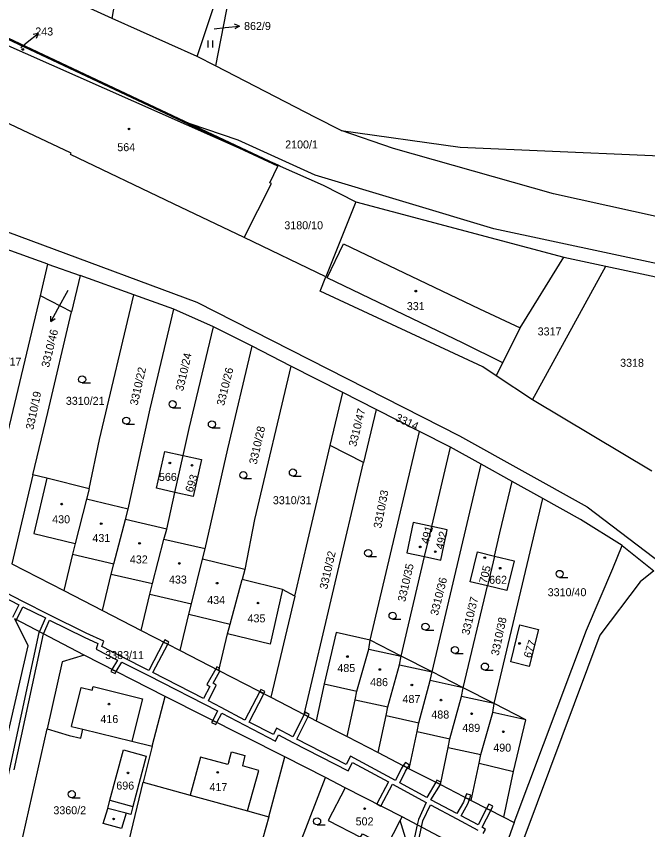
# Model space of a CAD drawing. Extents: x -776734 to -748832, y -1118122 to -976986.
# Drawn here: x -752629.9 to -752495.8, y -1114435.8 to -1114263.1 of the extents above; entities that cross this region are included whole.
import ezdxf

# ---------------------------------------------------------------- set-up
doc = ezdxf.new("R2010")
doc.units = 0
for name, color, linetype in [('KM_Hranice obce', 7, 'Continuous'), ('KM_Hranice parcel', 7, 'Continuous'), ('KM_Parcelní čísla', 7, 'Continuous'), ('KM_Pop  PČ popisy', 7, 'Continuous'), ('KM_Vnitřní kresba', 7, 'Continuous'), ('KM_Věcná břemena k části', 7, 'Continuous'), ('KM_Značky budov', 7, 'Continuous'), ('KM_Značky kultur', 7, 'Continuous')]:
    doc.layers.add(name, color=color, linetype=linetype)

msp = doc.modelspace()

# ---------------------------------------------------------------- linework, layer by layer
at = {"layer": 'KM_Hranice obce'}
for p, q in [((-752573.84, -1114294.91), (-752574.27, -1114294.72)), ((-752573.84, -1114294.91), (-752574.27, -1114294.72)), ((-752557.76, -1114302.48), (-752513.59, -1114314.26)), ((-752557.76, -1114302.48), (-752513.59, -1114314.26)), ((-752513.59, -1114314.26), (-752504.69, -1114316.16)), ((-752513.59, -1114314.26), (-752504.69, -1114316.16)), ((-752504.69, -1114316.16), (-752479.17, -1114321.6)), ((-752504.69, -1114316.16), (-752479.17, -1114321.6))]:
    msp.add_line(p, q, dxfattribs=at)
for points in [[(-752574.27, -1114294.72), (-752582.54, -1114291.06), (-752633.55, -1114268.51)], [(-752574.27, -1114294.72), (-752582.54, -1114291.06), (-752633.55, -1114268.51)], [(-752573.84, -1114294.91), (-752564.71, -1114298.94), (-752557.76, -1114302.48)], [(-752573.84, -1114294.91), (-752564.71, -1114298.94), (-752557.76, -1114302.48)]]:
    msp.add_lwpolyline(points, dxfattribs=at)
at = {"layer": 'KM_Hranice parcel'}
for p, q in [((-752609.53, -1114263.52), (-752605.61, -1114240.78)), ((-752591.45, -1114271.64), (-752581.12, -1114240.48)), ((-752581.12, -1114240.48), (-752587.58, -1114273.63)), ((-752609.53, -1114263.52), (-752614.99, -1114261.06)), ((-752591.45, -1114271.64), (-752609.53, -1114263.52)), ((-752587.58, -1114273.63), (-752591.45, -1114271.64)), ((-752557.76, -1114302.48), (-752564.12, -1114318.38)), ((-752564.12, -1114318.38), (-752581.45, -1114310.09)), ((-752623.16, -1114315.69), (-752632.76, -1114312.25)), ((-752624.76, -1114322.41), (-752623.16, -1114315.69)), ((-752623.16, -1114315.69), (-752616.33, -1114318.14)), ((-752520.23, -1114344.55), (-752504.69, -1114316.16)), ((-752616.33, -1114318.14), (-752618.14, -1114325.82)), ((-752604.94, -1114322.22), (-752616.33, -1114318.14)), ((-752565.36, -1114321.48), (-752564.12, -1114318.38)), ((-752632.38, -1114354.51), (-752624.76, -1114322.41)), ((-752618.14, -1114325.82), (-752624.76, -1114322.41)), ((-752596.44, -1114325.26), (-752604.94, -1114322.22)), ((-752587.97, -1114329), (-752596.44, -1114325.26)), ((-752579.81, -1114333.15), (-752587.97, -1114329)), ((-752571.56, -1114337.35), (-752579.81, -1114333.15)), ((-752560.54, -1114342.95), (-752571.56, -1114337.35)), ((-752520.23, -1114344.55), (-752527.93, -1114339.43)), ((-752563.2, -1114354.2), (-752560.54, -1114342.95)), ((-752553.44, -1114346.57), (-752560.54, -1114342.95)), ((-752494.88, -1114359.71), (-752520.23, -1114344.55)), ((-752553.44, -1114346.57), (-752556.11, -1114357.85)), ((-752544.26, -1114351.24), (-752553.44, -1114346.57)), ((-752554.74, -1114395.57), (-752544.26, -1114351.24)), ((-752537.67, -1114354.58), (-752544.26, -1114351.24)), ((-752556.11, -1114357.85), (-752563.2, -1114354.2)), ((-752541.65, -1114371.44), (-752537.67, -1114354.58)), ((-752531.12, -1114358.22), (-752537.67, -1114354.58)), ((-752596.18, -1114364.2), (-752594.42, -1114356.36)), ((-752568.76, -1114411.33), (-752556.11, -1114357.85)), ((-752541.56, -1114402.3), (-752531.12, -1114358.22)), ((-752524.6, -1114361.84), (-752531.12, -1114358.22)), ((-752626.32, -1114360.46), (-752630.78, -1114379.36)), ((-752518.06, -1114365.48), (-752524.6, -1114361.84)), ((-752614.36, -1114363.4), (-752614.94, -1114365.65)), ((-752606.12, -1114367.71), (-752614.94, -1114365.65)), ((-752597.93, -1114371.96), (-752596.18, -1114364.2)), ((-752528.37, -1114409.03), (-752518.06, -1114365.48)), ((-752606.7, -1114369.93), (-752606.12, -1114367.71)), ((-752597.93, -1114371.96), (-752606.7, -1114369.93)), ((-752598.5, -1114374.19), (-752597.93, -1114371.96)), ((-752543.16, -1114377.83), (-752541.65, -1114371.44)), ((-752589.73, -1114376.15), (-752598.5, -1114374.19)), ((-752590.29, -1114378.38), (-752589.73, -1114376.15)), ((-752501.24, -1114375.49), (-752494.46, -1114380.82)), ((-752548.15, -1114398.93), (-752543.16, -1114377.83)), ((-752533.49, -1114383.17), (-752531.93, -1114376.8)), ((-752531.93, -1114376.8), (-752528.34, -1114377.69)), ((-752528.34, -1114377.69), (-752529.84, -1114384.01)), ((-752528.34, -1114377.69), (-752524.11, -1114378.74)), ((-752630.78, -1114379.36), (-752619.77, -1114385.04)), ((-752581.34, -1114380.54), (-752590.29, -1114378.38)), ((-752524.11, -1114378.74), (-752525.69, -1114385.04)), ((-752581.34, -1114380.54), (-752581.91, -1114382.66)), ((-752534.96, -1114405.67), (-752529.84, -1114384.01)), ((-752529.84, -1114384.01), (-752533.49, -1114383.17)), ((-752525.69, -1114385.04), (-752529.84, -1114384.01)), ((-752619.77, -1114385.04), (-752611.55, -1114389.28)), ((-752570.75, -1114386.2), (-752575.83, -1114407.69)), ((-752611.55, -1114389.28), (-752603.32, -1114393.52)), ((-752615.48, -1114398.75), (-752630.14, -1114391.02)), ((-752603.32, -1114393.52), (-752595.07, -1114397.77)), ((-752548.15, -1114398.93), (-752554.74, -1114395.57)), ((-752595.07, -1114397.77), (-752586.84, -1114402.01)), ((-752598.27, -1114407.53), (-752615.48, -1114398.75)), ((-752541.56, -1114402.3), (-752548.15, -1114398.93)), ((-752586.84, -1114402.01), (-752575.83, -1114407.69)), ((-752534.96, -1114405.67), (-752541.56, -1114402.3)), ((-752528.37, -1114409.03), (-752534.96, -1114405.67)), ((-752601.02, -1114418.1), (-752598.27, -1114407.53)), ((-752572.82, -1114420.33), (-752598.27, -1114407.53)), ((-752575.83, -1114407.69), (-752568.76, -1114411.33)), ((-752559.58, -1114416.05), (-752557.93, -1114408.2)), ((-752568.76, -1114411.33), (-752566.16, -1114412.67)), ((-752553, -1114419.45), (-752551.35, -1114411.57)), ((-752566.16, -1114412.67), (-752559.58, -1114416.05)), ((-752629.82, -1114443.36), (-752623.31, -1114414.37)), ((-752546.42, -1114422.85), (-752544.77, -1114414.95)), ((-752559.58, -1114416.05), (-752553, -1114419.45)), ((-752601.02, -1114418.1), (-752602.95, -1114425.68)), ((-752539.82, -1114426.24), (-752538.19, -1114418.32)), ((-752576.24, -1114433.08), (-752572.82, -1114420.33)), ((-752564.22, -1114424.74), (-752572.82, -1114420.33)), ((-752553, -1114419.45), (-752546.42, -1114422.85)), ((-752533.24, -1114429.64), (-752531.61, -1114421.7)), ((-752546.42, -1114422.85), (-752539.82, -1114426.24)), ((-752608.32, -1114448.32), (-752602.95, -1114425.68)), ((-752560.02, -1114426.89), (-752564.22, -1114424.74)), ((-752539.82, -1114426.24), (-752533.24, -1114429.64)), ((-752547.94, -1114433.09), (-752560.02, -1114426.89)), ((-752533.24, -1114429.64), (-752526.31, -1114433.18)), ((-752576.24, -1114433.08), (-752582.04, -1114453.98)), ((-752548.32, -1114433.84), (-752547.94, -1114433.09)), ((-752537.93, -1114438.41), (-752547.94, -1114433.09)), ((-752524.15, -1114434.29), (-752527.55, -1114443.69)), ((-752526.31, -1114433.18), (-752524.15, -1114434.29))]:
    msp.add_line(p, q, dxfattribs=at)
for points in [[(-752633.55, -1114268.51), (-752632.97, -1114267.35), (-752632.83, -1114267.07), (-752592.94, -1114285.9), (-752573.84, -1114294.91)], [(-752560.87, -1114287.36), (-752566.33, -1114284.55), (-752587.58, -1114273.63)], [(-752581.45, -1114310.09), (-752596.49, -1114302.9), (-752618.37, -1114292.43), (-752618.24, -1114292.16), (-752618.35, -1114292.11), (-752640.12, -1114281.82)], [(-752475.76, -1114309.61), (-752515.81, -1114300.8), (-752549.74, -1114291.15), (-752560.87, -1114287.36)], [(-752560.87, -1114287.36), (-752535.58, -1114290.89), (-752476.78, -1114293.41), (-752418.52, -1114303.25), (-752354.79, -1114315), (-752350.02, -1114319.68), (-752294.72, -1114338.85)], [(-752581.45, -1114310.09), (-752575.68, -1114298.58), (-752576.02, -1114298.42), (-752574.36, -1114294.91), (-752574.27, -1114294.72)], [(-752674.06, -1114297.38), (-752657.12, -1114299.43), (-752591.55, -1114323.82), (-752535.77, -1114352.2), (-752508.64, -1114367.28), (-752477.04, -1114391.22), (-752438.72, -1114427.56), (-752434.8, -1114442.43), (-752427.57, -1114445.21)], [(-752527.93, -1114339.43), (-752526.54, -1114336.64), (-752522.9, -1114329.27), (-752513.59, -1114314.26)], [(-752614.36, -1114363.4), (-752612.19, -1114352.92), (-752604.94, -1114322.22)], [(-752527.93, -1114339.43), (-752530.78, -1114337.53), (-752565.36, -1114321.48)], [(-752626.32, -1114360.46), (-752623.2, -1114347.24), (-752618.14, -1114325.82)], [(-752606.12, -1114367.71), (-752601.45, -1114346.46), (-752596.44, -1114325.26)], [(-752594.42, -1114356.36), (-752593.13, -1114350.64), (-752587.97, -1114329)], [(-752589.73, -1114376.15), (-752584.96, -1114354.96), (-752579.81, -1114333.15)], [(-752571.56, -1114337.35), (-752579.26, -1114369.92), (-752581.34, -1114380.54)], [(-752570.75, -1114386.2), (-752568.25, -1114375.59), (-752563.2, -1114354.2)], [(-752596.18, -1114364.2), (-752600.09, -1114363.31), (-752598.31, -1114355.48), (-752594.42, -1114356.36)], [(-752594.42, -1114356.36), (-752590.52, -1114357.21), (-752592.3, -1114365.05), (-752596.18, -1114364.2)], [(-752614.36, -1114363.4), (-752623.4, -1114361.18), (-752626.32, -1114360.46)], [(-752528.34, -1114377.69), (-752527.18, -1114372.77), (-752524.6, -1114361.84)], [(-752614.94, -1114365.65), (-752617.35, -1114375.05), (-752617.92, -1114377.29), (-752619.77, -1114385.04)], [(-752501.24, -1114375.49), (-752510.09, -1114369.91), (-752518.06, -1114365.48)], [(-752611.55, -1114389.28), (-752609.75, -1114381.58), (-752609.17, -1114379.35), (-752606.7, -1114369.93)], [(-752541.65, -1114371.44), (-752545.61, -1114370.59), (-752546.93, -1114377.03), (-752543.16, -1114377.83)], [(-752543.16, -1114377.83), (-752539.74, -1114378.56), (-752538.36, -1114372.15), (-752541.65, -1114371.44)], [(-752603.32, -1114393.52), (-752601.48, -1114385.77), (-752600.91, -1114383.53), (-752598.5, -1114374.19)], [(-752524.15, -1114434.29), (-752508.77, -1114393.47), (-752503.22, -1114380.32), (-752501.24, -1114375.49)], [(-752595.07, -1114397.77), (-752593.2, -1114390.05), (-752592.64, -1114387.82), (-752590.29, -1114378.38)], [(-752494.46, -1114380.82), (-752497.39, -1114383.19), (-752505.97, -1114394.52), (-752524.72, -1114444.68), (-752553.86, -1114528.55)], [(-752586.84, -1114402.01), (-752585, -1114394.25), (-752584.44, -1114392.14), (-752581.91, -1114382.66)], [(-752570.75, -1114386.2), (-752573.33, -1114384.82), (-752581.91, -1114382.66)], [(-752631.89, -1114416.48), (-752627.31, -1114396.73), (-752630.14, -1114391.02)], [(-752524.87, -1114400.13), (-752522.93, -1114392.33), (-752519.01, -1114393.3), (-752520.95, -1114401.12), (-752524.87, -1114400.13)], [(-752554.74, -1114395.57), (-752561.95, -1114393.91), (-752564.52, -1114404.82), (-752566.16, -1114412.67)], [(-752557.93, -1114408.2), (-752557.53, -1114406.39), (-752555.02, -1114397.48), (-752554.74, -1114395.57)], [(-752615.48, -1114398.75), (-752620.11, -1114400.15), (-752623.31, -1114414.37)], [(-752551.35, -1114411.57), (-752550.95, -1114409.74), (-752548.47, -1114400.79), (-752548.15, -1114398.93)], [(-752544.77, -1114414.95), (-752544.37, -1114413.13), (-752541.95, -1114404.13), (-752541.56, -1114402.3)], [(-752538.19, -1114418.32), (-752537.79, -1114416.51), (-752535.3, -1114407.52), (-752534.96, -1114405.67)], [(-752531.61, -1114421.7), (-752531.2, -1114419.86), (-752528.68, -1114410.89), (-752528.37, -1114409.03)], [(-752526.31, -1114433.18), (-752524.27, -1114423.43), (-752521.68, -1114412.45), (-752528.37, -1114409.03)], [(-752623.31, -1114414.37), (-752618.62, -1114415.8), (-752616.19, -1114416.39), (-752615.72, -1114414.47), (-752605.33, -1114417.03), (-752601.02, -1114418.1)], [(-752602.26, -1114420.2), (-752605.1, -1114430.85), (-752605.55, -1114432.6), (-752606.55, -1114432.33), (-752607.51, -1114435.56), (-752611.39, -1114434.52), (-752610.43, -1114431.31), (-752610.01, -1114429.55), (-752607.13, -1114418.88), (-752602.26, -1114420.2)], [(-752602.95, -1114425.68), (-752592.93, -1114428.45), (-752580.78, -1114431.83), (-752576.24, -1114433.08)], [(-752558.89, -1114441.21), (-752569.58, -1114438.66), (-752564.22, -1114424.74)], [(-752560.02, -1114426.89), (-752563.62, -1114433.87), (-752556.75, -1114437.4), (-752556.38, -1114436.68), (-752554.56, -1114437.61), (-752558.89, -1114441.21)], [(-752548.1, -1114443.78), (-752546.92, -1114438.44), (-752548.32, -1114433.84)]]:
    msp.add_lwpolyline(points, dxfattribs=at)
at = {"layer": 'KM_Pop  PČ popisy'}
for p, q in [((-752587.88, -1114265.73), (-752585.48, -1114265.47)), ((-752585.48, -1114265.47), (-752582.495, -1114265.156)), ((-752582.495, -1114265.156), (-752583.544, -1114264.763)), ((-752582.495, -1114265.156), (-752583.439, -1114265.759)), ((-752627.56, -1114268.61), (-752625.195, -1114266.762)), ((-752625.195, -1114266.762), (-752626.293, -1114266.984)), ((-752625.195, -1114266.762), (-752625.676, -1114267.774)), ((-752628.93, -1114269.68), (-752627.56, -1114268.61)), ((-752618.92, -1114321.28), (-752621.1, -1114325.28)), ((-752621.1, -1114325.28), (-752622.555, -1114327.905)), ((-752622.555, -1114327.905), (-752622.507, -1114326.786)), ((-752622.555, -1114327.905), (-752621.631, -1114327.272))]:
    msp.add_line(p, q, dxfattribs=at)
at = {"layer": 'KM_Vnitřní kresba'}
for p, q in [((-752582.54, -1114291.06), (-752632.97, -1114267.35)), ((-752582.72, -1114289.38), (-752592.94, -1114285.9)), ((-752566.42, -1114296.81), (-752582.72, -1114289.38)), ((-752574.36, -1114294.91), (-752582.54, -1114291.06)), ((-752528.47, -1114308.24), (-752566.42, -1114296.81)), ((-752478.61, -1114318.89), (-752528.47, -1114308.24)), ((-752563.87, -1114318.64), (-752560.36, -1114311.37)), ((-752560.36, -1114311.37), (-752531.47, -1114325.17)), ((-752534.94, -1114332.48), (-752563.87, -1114318.64)), ((-752531.47, -1114325.17), (-752522.9, -1114329.27)), ((-752526.54, -1114336.64), (-752534.94, -1114332.48)), ((-752623.4, -1114361.18), (-752626.17, -1114372.93)), ((-752626.17, -1114372.93), (-752617.35, -1114375.05)), ((-752617.92, -1114377.29), (-752609.17, -1114379.35)), ((-752609.75, -1114381.58), (-752600.91, -1114383.53)), ((-752601.48, -1114385.77), (-752592.64, -1114387.82)), ((-752573.33, -1114384.82), (-752575.97, -1114396.42)), ((-752593.2, -1114390.05), (-752584.44, -1114392.14)), ((-752575.97, -1114396.42), (-752585, -1114394.25)), ((-752555.02, -1114397.48), (-752548.15, -1114398.93)), ((-752548.47, -1114400.79), (-752541.56, -1114402.3)), ((-752613.72, -1114406.16), (-752613.53, -1114405.43)), ((-752613.53, -1114405.43), (-752603.09, -1114407.99)), ((-752564.52, -1114404.82), (-752557.53, -1114406.39)), ((-752534.96, -1114405.67), (-752541.95, -1114404.13)), ((-752618.14, -1114413.88), (-752616.06, -1114405.59)), ((-752616.06, -1114405.59), (-752613.72, -1114406.16)), ((-752603.09, -1114407.99), (-752605.33, -1114417.03)), ((-752557.93, -1114408.2), (-752550.95, -1114409.74)), ((-752528.37, -1114409.03), (-752535.3, -1114407.52)), ((-752551.35, -1114411.57), (-752544.37, -1114413.13)), ((-752521.68, -1114412.45), (-752528.68, -1114410.89)), ((-752618.14, -1114413.88), (-752615.72, -1114414.47)), ((-752544.77, -1114414.95), (-752537.79, -1114416.51)), ((-752584.72, -1114421.43), (-752584.16, -1114419.3)), ((-752584.16, -1114419.3), (-752581.33, -1114420.05)), ((-752538.19, -1114418.32), (-752531.2, -1114419.86)), ((-752590.72, -1114420.39), (-752592.93, -1114428.45)), ((-752584.91, -1114421.99), (-752590.72, -1114420.39)), ((-752581.33, -1114420.05), (-752581.85, -1114422.26)), ((-752584.72, -1114421.43), (-752584.91, -1114421.99)), ((-752578.37, -1114423.26), (-752581.85, -1114422.26)), ((-752531.61, -1114421.7), (-752524.27, -1114423.43)), ((-752580.78, -1114431.83), (-752578.37, -1114423.26)), ((-752610.01, -1114429.55), (-752605.1, -1114430.85)), ((-752606.55, -1114432.33), (-752610.43, -1114431.31)), ((-752551.18, -1114439.35), (-752548.32, -1114433.84))]:
    msp.add_line(p, q, dxfattribs=at)
at = {"layer": 'KM_Věcná břemena k části'}
for points in [[(-752651.03, -1114376.83), (-752629.34, -1114388.03), (-752630.67, -1114390.74)], [(-752529.13, -1114431.74), (-752530.02, -1114431.29), (-752531.82, -1114434.78), (-752535.41, -1114432.84), (-752533.96, -1114430.35), (-752533.65, -1114429.43), (-752534.55, -1114428.96), (-752534.88, -1114429.93), (-752536.29, -1114432.37), (-752541.82, -1114429.45), (-752539.82, -1114426.24), (-752540.79, -1114425.74), (-752542.69, -1114428.95), (-752548.44, -1114425.85), (-752547.23, -1114423.35), (-752546.77, -1114422.67), (-752547.68, -1114422.2), (-752548.11, -1114422.85), (-752549.32, -1114425.36), (-752558.9, -1114420.21), (-752559.82, -1114421.94), (-752570.26, -1114416.57), (-752567.87, -1114411.79), (-752568.76, -1114411.33), (-752571.15, -1114416.12), (-752574.63, -1114414.26), (-752575.27, -1114415.62), (-752580.44, -1114412.98), (-752577.3, -1114406.93), (-752578.18, -1114406.48), (-752581.32, -1114412.52), (-752586.34, -1114409.88), (-752589.07, -1114408.45), (-752587.45, -1114405.09), (-752588.07, -1114404.68), (-752586.62, -1114402.12), (-752586.84, -1114402.01), (-752587.52, -1114401.66), (-752589.39, -1114405), (-752588.75, -1114405.43), (-752590.08, -1114407.94), (-752600.84, -1114402.42), (-752597.7, -1114396.42), (-752598.58, -1114395.96), (-752601.72, -1114401.97), (-752607.46, -1114399.12), (-752611.71, -1114396.94), (-752611.3, -1114395.78), (-752615.06, -1114394.04), (-752622.85, -1114390.16), (-752628.45, -1114387.36), (-752650.08, -1114376.19)], [(-752629.92, -1114391.47), (-752629.79, -1114391.21), (-752628.45, -1114388.48), (-752623.69, -1114390.85), (-752624.97, -1114393.75), (-752625.06, -1114393.95)], [(-752630.31, -1114423.1), (-752624.08, -1114394.21), (-752622.79, -1114391.3), (-752615.48, -1114394.95), (-752612.54, -1114396.3), (-752612.93, -1114397.44), (-752608.37, -1114399.78), (-752609.57, -1114401.77), (-752608.67, -1114402.22), (-752607.47, -1114400.23), (-752601.77, -1114403.07), (-752587.12, -1114410.6), (-752588.16, -1114412.61), (-752587.27, -1114413.06), (-752586.24, -1114411.07), (-752581.33, -1114413.64), (-752574.81, -1114416.98), (-752574.17, -1114415.64), (-752571.15, -1114417.26), (-752559.4, -1114423.28), (-752558.49, -1114421.57), (-752550.85, -1114425.67), (-752553.33, -1114430.32), (-752552.44, -1114430.78), (-752549.98, -1114426.16), (-752542.81, -1114430.02), (-752544.48, -1114433.64), (-752544.73, -1114434.79), (-752549.73, -1114457.68)], [(-752625.06, -1114393.95), (-752631.28, -1114422.86), (-752634.31, -1114436.29), (-752642.14, -1114434.5), (-752642.37, -1114435.47), (-752634.54, -1114437.27)], [(-752548.77, -1114457.99), (-752543.81, -1114435.29), (-752543.52, -1114433.96), (-752541.94, -1114430.53), (-752536.34, -1114433.47), (-752531.87, -1114435.89)], [(-752530.75, -1114436.61), (-752530.21, -1114435.77), (-752530.97, -1114435.28), (-752529.13, -1114431.74)]]:
    msp.add_lwpolyline(points, dxfattribs=at)
for points in [[(-752598.58, -1114395.96), (-752597.7, -1114396.42), (-752597.47, -1114395.98), (-752598.35, -1114395.52)], [(-752608.67, -1114402.22), (-752609.57, -1114401.77), (-752609.8, -1114402.21), (-752608.9, -1114402.67)], [(-752587.52, -1114401.66), (-752586.84, -1114402.01), (-752586.72, -1114401.52), (-752587.28, -1114401.22)], [(-752578.18, -1114406.48), (-752577.3, -1114406.93), (-752577.07, -1114406.49), (-752577.95, -1114406.04)], [(-752568.76, -1114411.33), (-752567.87, -1114411.79), (-752567.65, -1114411.34), (-752568.54, -1114410.88)], [(-752587.27, -1114413.06), (-752588.16, -1114412.61), (-752588.39, -1114413.05), (-752587.5, -1114413.5)], [(-752547.68, -1114422.2), (-752546.77, -1114422.67), (-752546.39, -1114422.09), (-752547.23, -1114421.53)], [(-752540.79, -1114425.74), (-752539.82, -1114426.24), (-752539.72, -1114425.74), (-752540.56, -1114425.3)], [(-752534.55, -1114428.96), (-752533.65, -1114429.43), (-752533.33, -1114428.48), (-752534.27, -1114428.16)], [(-752530.02, -1114431.29), (-752529.13, -1114431.74), (-752528.66, -1114430.82), (-752529.54, -1114430.36)]]:
    msp.add_lwpolyline(points, close=True, dxfattribs=at)
at = {"layer": 'KM_Značky budov'}
for centre in [(-752628.4868, -1114270.1192), (-752605.9268, -1114286.9992), (-752545.0368, -1114321.4492), (-752597.2568, -1114357.9392), (-752592.5368, -1114358.4292), (-752620.2168, -1114366.6792), (-752611.8368, -1114370.8192), (-752603.6868, -1114375.0092), (-752544.0868, -1114375.7492), (-752540.8868, -1114376.7792), (-752530.3768, -1114378.0292), (-752595.2568, -1114379.2792), (-752527.1168, -1114380.2892), (-752587.2168, -1114383.4592), (-752578.5268, -1114387.6692), (-752522.9968, -1114396.2592), (-752559.5468, -1114399.0392), (-752552.6668, -1114401.7892), (-752545.8668, -1114405.0792), (-752539.6768, -1114408.2892), (-752610.1868, -1114409.1492), (-752533.1768, -1114411.1992), (-752526.4468, -1114415.0192), (-752606.1608, -1114423.7468), (-752587.0868, -1114423.6292), (-752555.8968, -1114431.3592), (-752609.1968, -1114433.5192)]:
    msp.add_circle(centre, 0.175, dxfattribs=at)
at = {"layer": 'KM_Značky kultur'}
for p, q in [((-752589.121, -1114269.69), (-752589.121, -1114268.19)), ((-752588.12, -1114269.69), (-752588.12, -1114268.19)), ((-752615.883, -1114340.94), (-752614.133, -1114340.94)), ((-752596.673, -1114346.2), (-752594.923, -1114346.2)), ((-752606.523, -1114349.69), (-752604.773, -1114349.69)), ((-752588.333, -1114350.48), (-752586.583, -1114350.48)), ((-752581.653, -1114361.25), (-752579.903, -1114361.25)), ((-752571.133, -1114360.71), (-752569.383, -1114360.71)), ((-752555.143, -1114377.83), (-752553.393, -1114377.83)), ((-752514.493, -1114382.24), (-752512.743, -1114382.24)), ((-752549.963, -1114391.12), (-752548.213, -1114391.12)), ((-752542.973, -1114393.45), (-752541.223, -1114393.45)), ((-752536.733, -1114398.41), (-752534.983, -1114398.41)), ((-752530.363, -1114401.92), (-752528.613, -1114401.92)), ((-752618.083, -1114429.02), (-752616.333, -1114429.02)), ((-752565.993, -1114434.78), (-752564.243, -1114434.78))]:
    msp.add_line(p, q, dxfattribs=at)
for centre in [(-752615.8829, -1114340.1898), (-752596.6729, -1114345.4498), (-752606.5229, -1114348.9398), (-752588.3329, -1114349.7298), (-752581.6529, -1114360.4998), (-752571.1329, -1114359.9598), (-752555.1429, -1114377.0798), (-752514.4929, -1114381.4898), (-752549.9629, -1114390.3698), (-752542.9729, -1114392.6998), (-752536.7329, -1114397.6598), (-752530.3629, -1114401.1698), (-752618.0829, -1114428.2698), (-752565.9929, -1114434.0298)]:
    msp.add_circle(centre, 0.75, dxfattribs=at)

# ---------------------------------------------------------------- texts
at = {"layer": 'KM_Parcelní čísla'}
for s, p in [('243', (-752625.835, -1114267.16)), ('862/9', (-752581.5, -1114265.99)), ('2100/1', (-752572.767, -1114291.15)), ('564', (-752608.415, -1114291.73)), ('3180/10', (-752572.946, -1114308.31)), ('331', (-752546.94, -1114325.48)), ('3317', (-752519.16, -1114330.85)), ('3310/17', (-752636.99, -1114337.27)), ('3318', (-752501.64, -1114337.51)), ('3310/21', (-752619.34, -1114345.59)), ('566', (-752599.575, -1114361.75)), ('3310/31', (-752575.38, -1114366.69)), ('430', (-752622.24, -1114370.74)), ('431', (-752613.7, -1114374.72)), ('432', (-752605.75, -1114379.27)), ('433', (-752597.44, -1114383.54)), ('662', (-752529.455, -1114383.59)), ('3310/40', (-752517.02, -1114386.23)), ('434', (-752589.32, -1114387.89)), ('435', (-752580.76, -1114391.78)), ('3383/11', (-752610.98, -1114399.58)), ('485', (-752561.68, -1114402.33)), ('486', (-752554.73, -1114405.32)), ('487', (-752547.85, -1114408.91)), ('488', (-752541.73, -1114412.2)), ('416', (-752612, -1114413.16)), ('489', (-752535.16, -1114415.03)), ('490', (-752528.58, -1114419.24)), ('696', (-752608.625, -1114427.29)), ('417', (-752588.84, -1114427.6)), ('3360/2', (-752621.987, -1114432.53)), ('502', (-752557.8, -1114434.89))]:
    msp.add_text(s, height=1.7, dxfattribs=at).set_placement(p)
for s, rotation, p in [('3310/46', 76, (-752622.939, -1114337.769)), ('3310/24', 77, (-752594.451, -1114342.801)), ('3310/22', 77, (-752604.131, -1114345.821)), ('3310/26', 76, (-752585.725, -1114345.885)), ('3310/19', 78, (-752626.248, -1114350.976)), ('3310/47', 76, (-752557.685, -1114354.585)), ('3314', 335, (-752549.539, -1114348.89)), ('3310/28', 77, (-752578.831, -1114358.341)), ('693', 72, (-752592.44, -1114364.324)), ('3310/33', 79, (-752552.385, -1114371.942)), ('491', 74, (-752542.382, -1114375.244)), ('492', 76, (-752539.245, -1114376.395)), ('3310/32', 77, (-752563.861, -1114384.871)), ('3310/35', 77, (-752547.281, -1114387.531)), ('705', 76, (-752529.987, -1114383.631)), ('3310/36', 76, (-752540.345, -1114390.445)), ('3310/37', 76, (-752533.715, -1114394.585)), ('3310/38', 78, (-752527.438, -1114398.936)), ('677', 72, (-752520.58, -1114399.494))]:
    msp.add_text(s, height=1.7, rotation=rotation, dxfattribs=at).set_placement(p)

doc.saveas('drawing.dxf')
